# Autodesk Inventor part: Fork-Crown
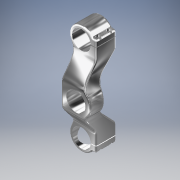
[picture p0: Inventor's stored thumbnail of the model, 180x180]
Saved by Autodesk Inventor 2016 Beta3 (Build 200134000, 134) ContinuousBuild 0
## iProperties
Shininess: 64.0
Length Units: 11272
Angle Units: 11279
Time Units: 11290
Mass Units: 11286
Length Display Precision: 3
Angle Display Precision: 2
Compacted: True
Created: 2001-11
Part Number: Fork-Crown
Document SubType Name: Modeling
Designer: Autodesk, Inc.
Mass: 96.105 g
Surface Area: 286.056 cm^2
Volume: 96.105 cm^3
Density: 1 g/cm^3
Material: Generic
Appearance: Chrome - Polished
Density: 0.0
Volumn: 0.0
Area: 0.0
PropertySet Name: Model Information
Control State: 0
Master: False
Checked Out: False
Author: Autodesk, Inc.
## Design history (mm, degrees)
sketch "Sketch1"
  geometry: L1 (387.107, 198.738)-(394.972, 198.738); L2 (387.081, 199.805)-(394.972, 199.805); L3 (394.972, 205.703)-(394.972, 199.805); L4 (390.064, 208.878)-(391.797, 208.878); L5 (362.993, 135.224)-(362.993, 160.563); L6 (394.972, 198.738)-(394.972, 166.433); L7 (362.993, 135.224)-(406.863, 135.224); L8 (362.993, 135.224)-(362.993, 109.884); L9 (387.081, 70.642)-(394.972, 70.642); L10 (394.972, 64.744)-(394.972, 70.642); L11 (390.064, 61.569)-(391.797, 61.569); L12 (387.107, 71.709)-(394.972, 71.709); L13 (394.972, 71.709)-(394.972, 104.014); A1 r 13.97 centre (373.138, 198.936) between (387.081, 199.805) and (387.107, 198.738); A2 r 3.175 centre (391.797, 205.703) between (394.972, 205.703) and (391.797, 208.878); A3 r 3.048 centre (390.064, 211.926) between (387.646, 210.07) and (390.064, 208.878); A4 r 18.288 centre (373.138, 198.936) between (387.646, 210.07) and (356.426, 191.509); A5 r 76.2 centre (286.793, 160.563) between (362.993, 160.563) and (356.426, 191.509); A6 r 25.4 centre (420.372, 166.433) between (394.972, 166.433) and (401.412, 149.532); A7 r 21.504 centre (385.359, 135.224) between (406.863, 135.224) and (401.412, 149.532); A8 r 76.2 centre (286.793, 109.884) between (356.426, 78.938) and (362.993, 109.884); A9 r 18.288 centre (373.138, 71.511) between (356.426, 78.938) and (387.646, 60.377); A10 r 3.175 centre (391.797, 64.744) between (391.797, 61.569) and (394.972, 64.744); A11 r 3.048 centre (390.064, 58.521) between (390.064, 61.569) and (387.646, 60.377); A12 r 13.97 centre (373.138, 71.511) between (387.107, 71.709) and (387.081, 70.642); A13 r 25.4 centre (420.372, 104.014) between (401.412, 120.915) and (394.972, 104.014); A14 r 21.504 centre (385.359, 135.224) between (401.412, 120.915) and (406.863, 135.224)
  constraints: 28 point on circle, 26 end point, 18 symmetric about line, 14 centre point, 8 tangent, 3 horizontal, 3 vertical, 1 collinear, 1 concentric, 1 horizontal alignment, 1 perpendicular, 15 other
  dimensions: "d1" = 13.97 radius of A1; "d7" = 76.2 radius of A5; "d9" = 18.288 radius of A4; "d92" = 3.175 radius of A2; "d94" = 5.89767 distance from line of A2.centre L2; "d95" = 1.06735 distance between parallel lines of L2 L1; "d99" = 12.2212 horizontal distance of A7.centre A1.centre; "d100" = 25.4 radius of A6; "d101" = 21.50376 radius of A7; "d102" = 3.048 radius of A3; "d103" = 25.33944 distance of L5.start L5.end; "d104" = 43.87007 distance of L5.start L7.end
extrude "ExtrusionBlind1" new body sketch "Sketch1" distance "d16" = 76.2; taper "d17" = 0 deg
node "WorkPlane1"
workaxis "Work Axis4"
sketch "Sketch9"
  geometry: L1 (28.214, 35.429)-(47.471, 16.806); L2 (47.471, 16.806)-(82.009, 16.806); L3 (82.009, 47.286)-(45.305, 47.286); L4 (45.305, 47.286)-(19.099, 67.761); L5 (19.099, 67.761)-(0.009, 67.761); L6 (0.009, 45.941)-(0.009, 67.761); L7 (0.009, -15.24)-(0.009, 91.44) reference; L8 (25.348, 76.2)-(-25.331, 76.2) reference; L9 (82.009, 0)-(82.009, 76.2) reference; L10 (-25.331, 0)-(25.348, 0) reference; L11 (-28.197, 35.429)-(-47.454, 16.806); L12 (-45.288, 47.286)-(-19.081, 67.761); L13 (-19.081, 67.761)-(0.009, 67.761); L14 (0.009, 45.941)-(0.009, 67.761); L15 (-81.992, 47.286)-(-45.288, 47.286); L16 (-47.454, 16.806)-(-81.992, 16.806); L17 (-81.992, 0)-(-81.992, 76.2) reference; A1 r 37.592 centre (2.081, 8.406) between (28.214, 35.429) and (0.009, 45.941); A2 r 37.592 centre (-2.064, 8.406) between (0.009, 45.941) and (-28.197, 35.429)
  constraints: 24 end point, 5 point on line, 5 symmetric about line, 4 point on circle, 3 horizontal, 2 centre point, 1 tangent, 1 vertical, 7 other
  dimensions: "d26" = 30.48 vertical distance of L1.end L3.end; "d30" = 37.592 radius of A1; "d105" = 8.43916 distance between parallel lines of L5 L8; "d106" = 8.40601 distance from line of L10 A1.centre; "d108" = 142 deg angle of L4 L5; "d109" = 19.09001 distance of L4.end L5.end; "d110" = 20.47486 distance between parallel lines of L5 L3; "d111" = 135.959 deg angle of L2 L1
extrude "ExtrusionThru1" sketch "Sketch9" stored distance "d35" = 3.302; taper "d36" = 0 deg
fillet "Fillet1" dims "d38" = 12.7
fillet "Fillet3" dims "d73" = 6.35
sketch "Sketch15"
  geometry: L1 (6.35, -28.694)-(6.35, -5.08); L2 (6.35, -5.08)-(29.21, -5.08); L3 (0, 16.052)-(0, 0) reference; L4 (35.262, 0)-(0, 0) reference; A1 r 19.05 centre (9.613, -47.462) between (22.86, -33.772) and (6.35, -28.694); A2 r 76.2 centre (99.038, -35.583) between (29.21, -5.08) and (22.86, -33.772); A3 r 21.504 centre (9.613, -47.462) between (-6.439, -33.154) and (-6.439, -61.771) reference; 3 further points
  constraints: 4 end point, 4 point on circle, 2 centre point, 1 coincident, 1 perpendicular, 2 other
  dimensions: "d113" = 6.35 distance between parallel lines of L1 L3; "d114" = 5.08 distance between parallel lines of L4 L2; "d115" = 76.2 radius of A2; "d116" = 22.86 distance of L1.end L2.end; "d117" = 19.05 radius of A1; "d118" = 6.35 horizontal distance of A1.start L2.end
extrude "Extrusion4" cut sketch "Sketch15" distance "d75" = 25.4; taper "d76" = 0 deg
fillet "Fillet5" dims "d77" = 5.08
workplane "Work Plane5"
mirror "Mirror1"
sketch "Sketch16"
  geometry: L1 (-22.366, 14.717)-(15.696, 14.717) reference; L2 (-22.366, 14.717)-(-22.366, -14.717) reference; L3 (15.696, -14.717)-(-22.366, -14.717) reference; A1 r 25.4 centre (35.013, -31.21) between (16.052, -14.309) and (15.696, -14.717) reference; A2 r 21.504 centre (0, 0) between (16.052, -14.309) and (16.052, 14.309) reference; A3 r 25.4 centre (35.013, 31.21) between (15.696, 14.717) and (16.052, 14.309) reference
hole "Hole6" sketch "Sketch16" at (0, 0) diameter "d80" = 28.575; stored, may be unused: countersink angle "d84" = 82 deg, drill point angle "d86" = 118 deg; dims "d81" = 12.7, "d82" = 9.525, "d83" = 6.35, "d85" = 19.05
fillet "Fillet6" dims "d120" = 2.54
workplane "Work Plane6"
sketch "Sketch18"
  geometry: L1 (-21.834, 19.346)-(-21.834, 44.746) reference; 2 further points
  constraints: 1 vertical alignment
  dimensions: "d121" = 15.875 distance of point (-18.659, 24.052) point (-18.659, 39.927); "d129" = 3.175 distance from line of point (-18.659, 39.927) L1
hole "Hole7" sketch "Sketch18" at (-18.659, 39.927), (-18.659, 24.052) diameter "d122" = 3.2512; stored, may be unused: countersink angle "d126" = 82 deg, drill point angle "d128" = 118 deg; dims "d123" = 12.7, "d124" = 6.35, "d125" = 11.43, "d127" = 25.4
mirror "Mirror2"
body "Solid1"
node "Projected Loop1"
other parameters: "mdtd132" = 1.3 [user parameter], "mdtd133" = 3.8 [user parameter], "mdtd136" = 1 [user parameter], "d0" = 14.732 (derived), "d2" = 127 (derived), "d4" = 20.574 (derived), "d6" = 76.2 (derived), "d8" = 18.288 (derived), "d10" = 1.016 (derived), "d12" = 25.4 (derived), "d14" = 23.622 (derived), "d18" = 0, "d19" = 0, "d20" = 0, "d21" = 0, "d22" = 0, "d23" = 0, "d25" = 30.48 (derived), "d27" = 38.354 (derived), "d29" = 37.592 (derived), "d31" = 50.8 (derived), "d33" = 142 deg (derived), "d37" = 0, "d39" = 0, "Hole" = 28.575 [user parameter], "d119" = 0
